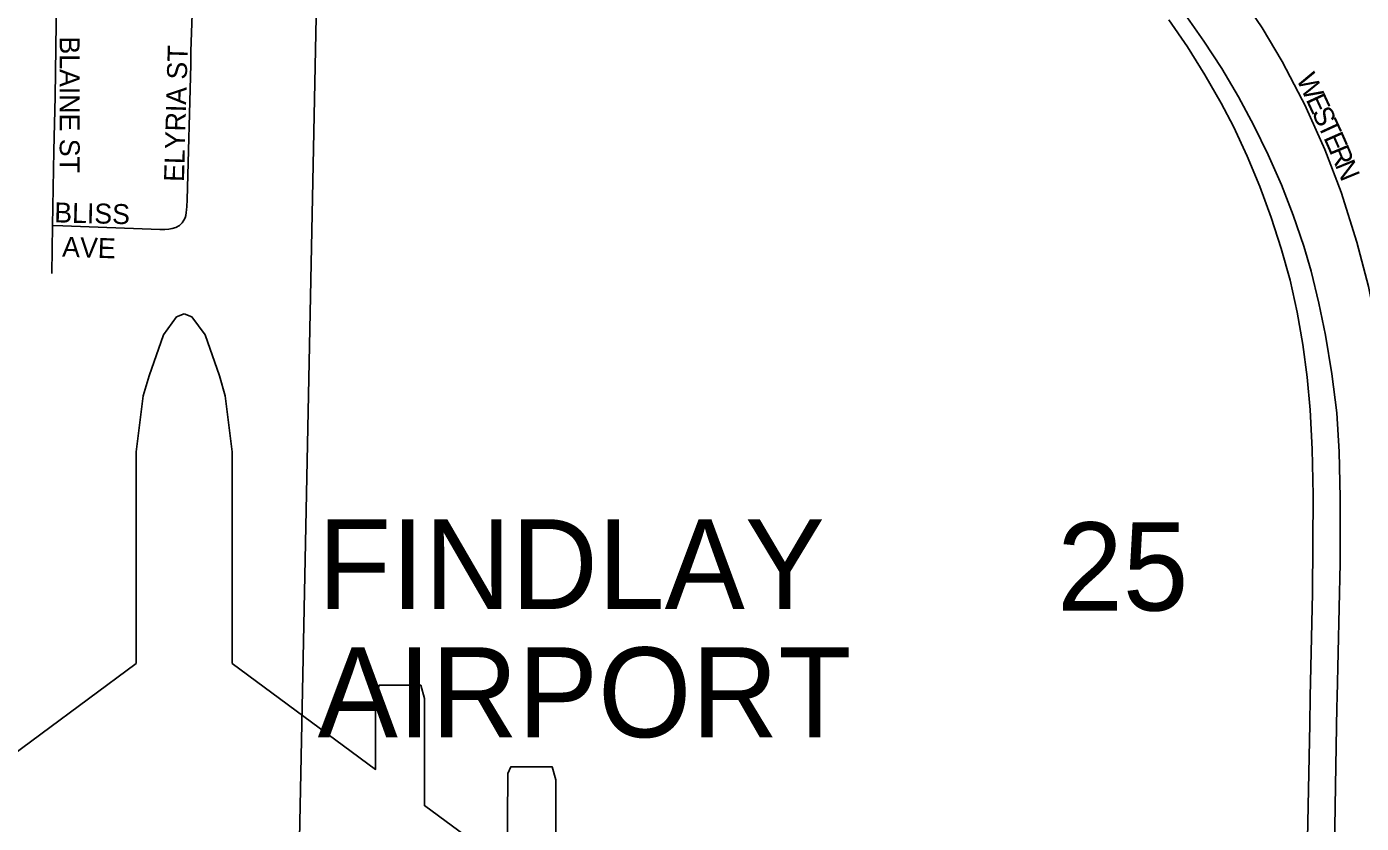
# Model space of a CAD drawing. Extents: x 0 to 68, y 0 to 52.9.
# Drawn here: x 41.67 to 42.505, y 39.867 to 40.366 of the extents above; entities that cross this region are included whole.
import ezdxf

# ---------------------------------------------------------------- set-up
doc = ezdxf.new("R2010")
doc.units = 0
doc.layers.add('Default', color=7, linetype='Continuous')

msp = doc.modelspace()

# ---------------------------------------------------------------- linework, layer by layer
at = {"layer": 'Default'}
msp.add_lwpolyline([(43.18298, 40.60237), (43.18329, 40.58736), (43.1609, 39.26536), (41.82896, 39.29088), (41.85592, 40.61931)], close=True, dxfattribs=at)
for points in [[(41.7652, 40.24142), (41.76698, 40.24298), (41.76801, 40.24476), (41.76874, 40.24622), (41.76916, 40.24768), (41.76947, 40.24944), (41.76968, 40.25121), (41.76978, 40.25329), (41.76999, 40.25746), (41.77237, 40.34216), (41.77242, 40.35038), (41.77314, 40.37396), (41.77622, 40.46316), (41.7765, 40.47126)], [(42.49024, 39.94586), (42.49201, 40.02985), (42.49218, 40.07088), (42.49152, 40.09956), (42.48992, 40.12408), (42.48695, 40.14845), (42.48293, 40.1727), (42.47879, 40.19276), (42.47386, 40.21264), (42.4693, 40.22836), (42.46276, 40.24775), (42.45536, 40.26683), (42.44707, 40.28554), (42.43803, 40.30392), (42.42835, 40.32196), (42.41792, 40.33959), (42.40682, 40.35679), (42.39502, 40.37352), (42.38254, 40.38976), (42.36948, 40.40552), (42.35575, 40.4207), (42.34137, 40.43528), (42.32346, 40.4521), (42.30696, 40.4666)], [(42.47087, 40.31515), (42.45587, 40.34416), (42.44328, 40.36521), (42.42711, 40.38885), (42.41432, 40.40602), (42.40732, 40.41495), (42.40023, 40.42361), (42.38792, 40.43729), (42.37609, 40.45046), (42.36202, 40.46517)], [(41.68581, 40.24125), (41.68659, 40.28801), (41.68743, 40.32207), (41.68803, 40.36782), (41.6882, 40.40146)], [(42.47095, 39.82647), (42.47306, 39.92896), (42.4734, 39.94614), (42.47469, 40.01097), (42.47519, 40.07251), (42.47465, 40.10125), (42.47331, 40.12587), (42.47145, 40.14633), (42.46873, 40.16671), (42.46518, 40.18696), (42.4607, 40.20703), (42.45521, 40.22684), (42.44887, 40.2464), (42.4418, 40.2657), (42.43396, 40.28471), (42.42528, 40.30335), (42.41766, 40.31793), (42.40744, 40.33576), (42.39652, 40.35318), (42.38488, 40.37012)], [(42.51262, 39.96323), (42.51624, 40.13838), (42.51547, 40.16699), (42.51374, 40.1832), (42.50991, 40.20323), (42.50261, 40.23094), (42.49271, 40.26215), (42.48258, 40.28894), (42.4709, 40.31508), (42.47087, 40.31515)], [(41.68531, 40.21123), (41.68581, 40.24125)], [(41.68581, 40.24125), (41.69214, 40.24108), (41.75291, 40.23892), (41.75614, 40.23892), (41.75854, 40.23912), (41.76062, 40.23954), (41.76302, 40.24017), (41.7652, 40.24142)], [(41.53544, 39.81713), (41.53544, 39.89408), (41.5378, 39.90224), (41.56371, 39.90224), (41.56551, 39.89816), (41.56607, 39.83978), (41.61777, 39.87801), (41.61777, 39.94516), (41.62013, 39.95333), (41.64603, 39.95333), (41.64839, 39.94516), (41.64839, 39.90066), (41.73816, 39.96703), (41.73816, 40.09965), (41.74254, 40.13473), (41.74619, 40.14722), (41.75518, 40.17276), (41.76348, 40.18411), (41.76822, 40.1861)], [(41.76822, 40.1861), (41.77296, 40.18411), (41.78126, 40.17276), (41.79025, 40.14722), (41.79391, 40.13472), (41.79829, 40.09965), (41.79829, 39.96703), (41.88805, 39.90066), (41.88805, 39.94516), (41.89041, 39.95333), (41.91632, 39.95333), (41.91868, 39.94516), (41.91868, 39.87801), (41.97038, 39.83978), (41.97093, 39.89816), (41.97274, 39.90224), (41.99865, 39.90224), (42.00101, 39.89408), (42.00101, 39.81713)], [(42.51319, 38.8091), (42.50865, 38.82219), (42.50147, 38.84579), (42.4947, 38.87162), (42.48976, 38.89372), (42.48519, 38.91797), (42.48078, 38.94641), (42.47788, 38.97091), (42.47558, 38.9996), (42.47447, 39.02424), (42.47414, 39.05302), (42.47546, 39.14334), (42.47758, 39.26648), (42.48007, 39.3978), (42.48199, 39.50863), (42.48378, 39.60713), (42.48523, 39.68101), (42.48802, 39.81233), (42.48915, 39.89031), (42.49011, 39.93957), (42.49024, 39.94586)]]:
    msp.add_lwpolyline(points, dxfattribs=at)

# ---------------------------------------------------------------- texts
for s, height, rotation, p in [('BLAINE ST', 0.0125, 270, (41.69025, 40.35977)), ('ELYRIA ST', 0.0125, 88.38732, (41.76805, 40.26854)), ('W', 0.0125, 294.75284, (42.46443, 40.33326)), ('E', 0.0125, 294.79561, (42.47043, 40.32026)), ('S', 0.0125, 294.75606, (42.47411, 40.31227)), ('T', 0.0125, 294.75604, (42.4778, 40.30428)), ('E', 0.0125, 293.91256, (42.48146, 40.29634)), ('R', 0.0125, 292.5545, (42.485, 40.28837)), ('N', 0.0125, 292.23984, (42.48879, 40.27924)), ('BLISS', 0.0125, 358.52662, (41.68672, 40.24333)), ('AVE', 0.0125, 358.08454, (41.69166, 40.22184)), ('FINDLAY', 0.05625, 0.00001, (41.8518, 40.00115)), ('25', 0.05525, 0.00001, (42.3149, 40.00015)), ('AIRPORT', 0.05625, 0.00001, (41.8518, 39.92084))]:
    msp.add_text(s, height=height, rotation=rotation, dxfattribs=at).set_placement(p)

doc.saveas('drawing.dxf')
